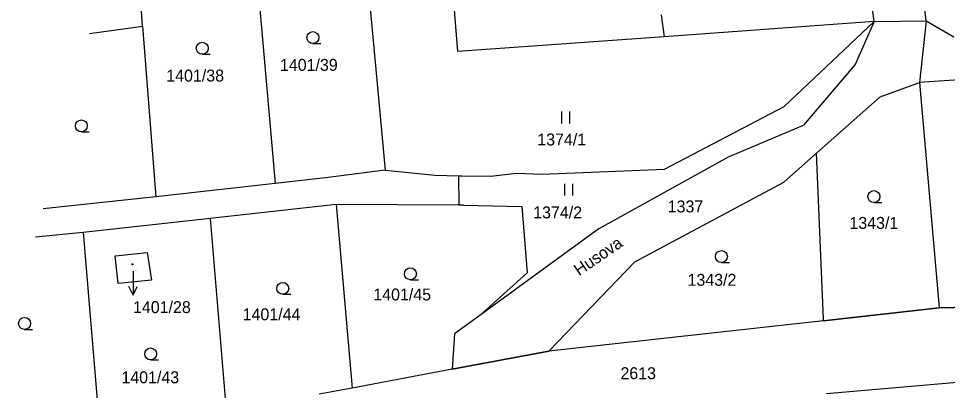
# Model space of a CAD drawing. Extents: x -805011 to -803920, y -1150790 to -1150234.
# Drawn here: x -804789.6 to -804673, y -1150515.7 to -1150469 of the extents above; entities that cross this region are included whole.
import ezdxf

# ---------------------------------------------------------------- set-up
doc = ezdxf.new("R2010")
doc.units = 0
for name, color, linetype in [('Default', 7, 'Continuous'), ('kn_celek - Cisla parcel pomocna', 7, 'Continuous'), ('kn_celek - Cisla pozemkovych parcel', 7, 'Continuous'), ('kn_celek - Cisla stavebnich parcel', 7, 'Continuous'), ('kn_celek - Dalsi prvky mapy popis', 7, 'Continuous'), ('kn_celek - Hranice parcel', 7, 'Continuous'), ('kn_celek - Znacky budov', 7, 'Continuous'), ('kn_celek - Znacky kultur', 7, 'Continuous'), ('plochy - SZDC', 7, 'Continuous'), ('PSR_C2_2_trasa_Vimperk - Kabelová trasa', 7, 'Continuous')]:
    doc.layers.add(name, color=color, linetype=linetype)

# ---------------------------------------------------------------- blocks, each defined once
blk = doc.blocks.new('304')
at = {"layer": 'Default'}
blk.add_line((-0.1, 0), (9.9, 0), dxfattribs=at)
blk.add_circle((-0.1, 7.5), 7.5, dxfattribs=at)
blk = doc.blocks.new('306')
at = {"layer": 'Default'}
for p, q in [((-5.2, 0), (-5.2, 15)), ((4.8, 0), (4.8, 15))]:
    blk.add_line(p, q, dxfattribs=at)
blk = doc.blocks.new('402')
at = {"layer": 'Default'}
for p, q in [((-0.8, 0.8), (0.7, 0.8)), ((-0.8, 0.8), (-0.8, -0.7)), ((0.7, 0.8), (0.7, -0.7)), ((0.7, -0.7), (-0.8, -0.7))]:
    blk.add_line(p, q, dxfattribs=at)
blk = doc.blocks.new('Z61')
at = {"layer": 'Default'}
for p, q in [((0, 0), (30, 0)), ((30, 0), (19.2, 5.3)), ((30, 0), (19.2, -5.3))]:
    blk.add_line(p, q, dxfattribs=at)

msp = doc.modelspace()

# ---------------------------------------------------------------- linework, layer by layer
at = {"layer": 'kn_celek - Hranice parcel'}
for p, q in [((-804675.65, -1150469.27), (-804678.11, -1150448.38)), ((-804734.44, -1150473.15), (-804736.15, -1150451.78)), ((-804746, -1150461.9), (-804743.58, -1150488.04)), ((-804759.6, -1150464.51), (-804757.39, -1150489.7)), ((-804774.01, -1150469.95), (-804774.23, -1150466.84)), ((-804682.2, -1150469.39), (-804682.45, -1150467.4)), ((-804708.92, -1150468.54), (-804708.56, -1150471.29)), ((-804682.2, -1150469.39), (-804708.56, -1150471.29)), ((-804693.49, -1150480.06), (-804682.2, -1150469.39)), ((-804682.2, -1150469.39), (-804684.56, -1150474.78)), ((-804682.2, -1150469.39), (-804675.65, -1150469.27)), ((-804675.65, -1150469.27), (-804676.51, -1150477.02)), ((-804675.65, -1150469.27), (-804672.2, -1150471.3)), ((-804780.68, -1150470.86), (-804774.01, -1150469.95)), ((-804774.01, -1150469.95), (-804772.35, -1150491.38)), ((-804708.56, -1150471.29), (-804734.44, -1150473.15)), ((-804684.56, -1150474.78), (-804691.04, -1150482.4)), ((-804661.91, -1150476.04), (-804676.51, -1150477.02)), ((-804681.43, -1150478.82), (-804676.51, -1150477.02)), ((-804676.51, -1150477.02), (-804674.03, -1150505.33)), ((-804689.41, -1150485.9), (-804681.43, -1150478.82)), ((-804708.52, -1150487.91), (-804693.49, -1150480.06)), ((-804700.46, -1150486.35), (-804691.04, -1150482.4)), ((-804693.5, -1150489.53), (-804689.41, -1150485.9)), ((-804688.56, -1150506.71), (-804689.41, -1150485.9)), ((-804716.68, -1150495.36), (-804700.46, -1150486.35)), ((-804743.58, -1150488.04), (-804751.05, -1150489)), ((-804743.58, -1150488.04), (-804737.31, -1150488.66)), ((-804723.84, -1150488.54), (-804708.52, -1150487.91)), ((-804751.05, -1150489), (-804757.39, -1150489.7)), ((-804737.31, -1150488.66), (-804734.35, -1150488.75)), ((-804734.35, -1150488.75), (-804733.93, -1150488.77)), ((-804734.35, -1150488.75), (-804734.33, -1150492.45)), ((-804733.93, -1150488.77), (-804730.3, -1150488.79)), ((-804730.3, -1150488.79), (-804727.07, -1150488.42)), ((-804727.07, -1150488.42), (-804723.84, -1150488.54)), ((-804712.24, -1150499.55), (-804693.5, -1150489.53)), ((-804757.39, -1150489.7), (-804772.35, -1150491.38)), ((-804772.35, -1150491.38), (-804786.51, -1150492.91)), ((-804749.71, -1150492.36), (-804765.53, -1150494.1)), ((-804734.33, -1150492.45), (-804749.71, -1150492.36)), ((-804749.71, -1150492.36), (-804747.72, -1150515.43)), ((-804733.75, -1150492.46), (-804734.33, -1150492.45)), ((-804733.75, -1150492.46), (-804726.41, -1150492.61)), ((-804726.41, -1150492.61), (-804725.72, -1150500.94)), ((-804765.53, -1150494.1), (-804781.47, -1150495.86)), ((-804765.53, -1150494.1), (-804763.55, -1150517.73)), ((-804716.68, -1150495.36), (-804731.68, -1150506.29)), ((-804781.47, -1150495.86), (-804787.45, -1150496.46)), ((-804781.47, -1150495.86), (-804779.51, -1150519.42)), ((-804777.46, -1150498.82), (-804773.44, -1150498.4)), ((-804777.09, -1150502.3), (-804777.46, -1150498.82)), ((-804773.44, -1150498.4), (-804772.89, -1150501.85)), ((-804723.03, -1150510.78), (-804712.24, -1150499.55)), ((-804725.72, -1150500.94), (-804731.68, -1150506.29)), ((-804772.89, -1150501.85), (-804777.09, -1150502.3)), ((-804688.55, -1150506.95), (-804674.03, -1150505.33)), ((-804674.03, -1150505.33), (-804659.84, -1150505.09)), ((-804731.68, -1150506.29), (-804734.86, -1150508.61)), ((-804688.55, -1150506.95), (-804723.03, -1150510.78)), ((-804688.55, -1150506.95), (-804688.56, -1150506.71)), ((-804734.86, -1150508.61), (-804735.17, -1150513.06)), ((-804735.17, -1150513.06), (-804723.03, -1150510.78)), ((-804735.17, -1150513.06), (-804747.72, -1150515.43)), ((-804747.72, -1150515.43), (-804751.83, -1150516.2))]:
    msp.add_line(p, q, dxfattribs=at)
at = {"layer": 'plochy - SZDC'}
for p, q in [((-804674.03, -1150505.33), (-804688.55, -1150506.95)), ((-804659.84, -1150505.09), (-804674.03, -1150505.33)), ((-804688.55, -1150506.95), (-804723.03, -1150510.78)), ((-804723.03, -1150510.78), (-804735.17, -1150513.06)), ((-804735.17, -1150513.06), (-804747.72, -1150515.43)), ((-804747.72, -1150515.43), (-804751.83, -1150516.2))]:
    msp.add_line(p, q, dxfattribs=at)
at = {"layer": 'PSR_C2_2_trasa_Vimperk - Kabelová trasa'}
msp.add_line((-804688.16, -1150516.11), (-804664.5, -1150514.01), dxfattribs=at)

# ---------------------------------------------------------------- block references
at = {"layer": 'kn_celek - Cisla parcel pomocna', "xscale": 0.1, "yscale": 0.10000000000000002, "rotation": -90.00000000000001}
msp.add_blockref('Z61', (-804775.21, -1150500.75), dxfattribs=at)
at = {"layer": 'kn_celek - Znacky budov', "xscale": 0.1, "yscale": 0.10000000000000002}
msp.add_blockref('402', (-804775.3, -1150499.88), dxfattribs=at)
at = {"layer": 'kn_celek - Znacky kultur', "xscale": 0.1, "yscale": 0.10000000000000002}
for name, p in [('304', (-804752.63, -1150472.14)), ('304', (-804766.52, -1150473.48)), ('306', (-804720.85, -1150482.18)), ('304', (-804781.69, -1150483.23)), ('306', (-804720.49, -1150491.24)), ('304', (-804682.21, -1150492.11)), ('304', (-804701.35, -1150499.64)), ('304', (-804740.38, -1150501.81)), ('304', (-804756.41, -1150503.64)), ('304', (-804788.82, -1150508.05)), ('304', (-804772.99, -1150511.88))]:
    msp.add_blockref(name, p, dxfattribs=at)

# ---------------------------------------------------------------- texts
at = {"layer": 'kn_celek - Cisla parcel pomocna'}
msp.add_text('1401/28', height=1.5, dxfattribs=at).set_placement((-804775.21, -1150506))
at = {"layer": 'kn_celek - Cisla pozemkovych parcel'}
for s, p in [('1401/39', (-804756.77, -1150475.57)), ('1401/38', (-804771.04, -1150476.91)), ('1374/1', (-804724.47, -1150484.94)), ('1337', (-804708.1, -1150493.35)), ('1374/2', (-804724.98, -1150494.1)), ('1343/1', (-804685.29, -1150495.42)), ('1343/2', (-804705.61, -1150502.57)), ('1401/45', (-804745.05, -1150504.41)), ('1401/44', (-804761.45, -1150506.9)), ('2613', (-804714.03, -1150514.3)), ('1401/43', (-804776.67, -1150514.81))]:
    msp.add_text(s, height=1.5, dxfattribs=at).set_placement(p)
at = {"layer": 'kn_celek - Cisla stavebnich parcel'}
msp.add_text('1401/28', height=0.1, dxfattribs=at).set_placement((-804775.21, -1150500.72))
at = {"layer": 'kn_celek - Dalsi prvky mapy popis'}
msp.add_text('Husova', height=1.5, rotation=34.4448, dxfattribs=at).set_placement((-804719.22, -1150501.38))

doc.saveas('drawing.dxf')
